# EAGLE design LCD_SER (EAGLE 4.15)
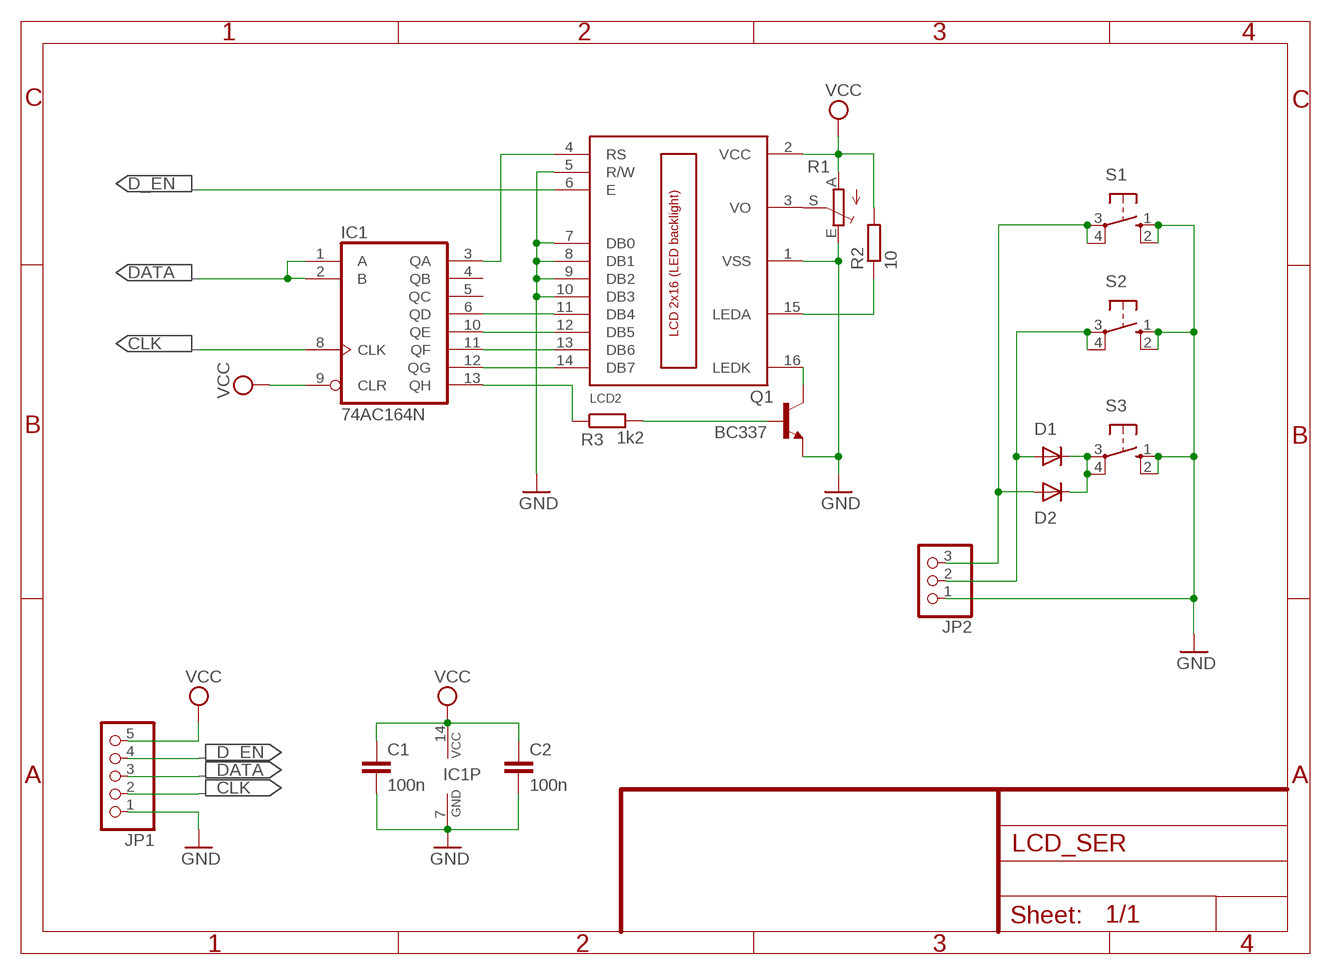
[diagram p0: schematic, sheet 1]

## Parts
C1  100n  C-EU025-025X050  [C025-025X050]
C2  100n  C-EU025-025X050  [C025-025X050]
D1  1N4148  [DO35-10]
D2  1N4148  [DO35-10]
IC1  74AC164N  [DIL14]
JP1  PINHD-1X5  [1X05]
JP2  PINHD-1X3  [1X03]
LCD2  LCD_2X16  [HY-1602F]
Q1  BC337  BC337-16  [TO92]
R1  TRIM_EU-PT10  [PT-10]
R2  10  R-EU_0207/10  [0207/10]
R3  1k2  R-EU_0207/10  [0207/10]
S1  10-XX  [B3F-10XX]
S2  10-XX  [B3F-10XX]
S3  10-XX  [B3F-10XX]

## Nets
CLK: IC1.8(CLK) JP1.2
D_EN: JP1.4 LCD2.6(E)
DATA: IC1.1(A) IC1.2(B) JP1.3
GND: C1.2 C2.2 IC1.7(GND) JP1.1 JP2.1 LCD2.1(VSS) LCD2.5(R/W) LCD2.7(DB0) LCD2.8(DB1) LCD2.9(DB2) LCD2.10(DB3) Q1.1(E) R1.E S1.1(S) S1.2(S1) S2.1(S) S2.2(S1) S3.1(S) S3.2(S1)
N$1: IC1.6(QD) LCD2.11(DB4)
N$2: IC1.10(QE) LCD2.12(DB5)
N$3: IC1.11(QF) LCD2.13(DB6)
N$4: IC1.12(QG) LCD2.14(DB7)
N$5: LCD2.16(LEDK) Q1.3(C)
N$6: IC1.3(QA) LCD2.4(RS)
N$7: LCD2.15(LEDA) R2.1
N$8: IC1.13(QH) R3.1
N$9: LCD2.3(VO) R1.S
N$10: Q1.2(B) R3.2
N$12: D1.C D2.C S3.3(P) S3.4(P1)
N$13: D1.A JP2.2 S2.3(P) S2.4(P1)
N$14: D2.A JP2.3 S1.3(P) S1.4(P1)
VCC: C1.1 C2.1 IC1.9(CLR) IC1.14(VCC) JP1.5 LCD2.2(VCC) R1.A R2.2
Unconnected: IC1.4(QB) IC1.5(QC)

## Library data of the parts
C1 C2 = rcl:C-EU: CAPACITOR, European symbol
D1 D2 = diode:1N4148: DIODE
IC1 = 74xx-eu:74*164: 8-bit parallel out SHIFT REGISTER
JP1 = pinhead:PINHD-1X5: PIN HEADER
JP2 = pinhead:PINHD-1X3: PIN HEADER
LCD2 = lcd_2x16_led_backlight:LCD_2X16
Q1 = transistor-npn:BC337*: NPN Transistor
R1 = pot:TRIM_EU-: POTENTIOMETER
R2 R3 = rcl:R-EU_: RESISTOR, European symbol
S1-S3 = switch-omron:10-XX: OMRON SWITCH

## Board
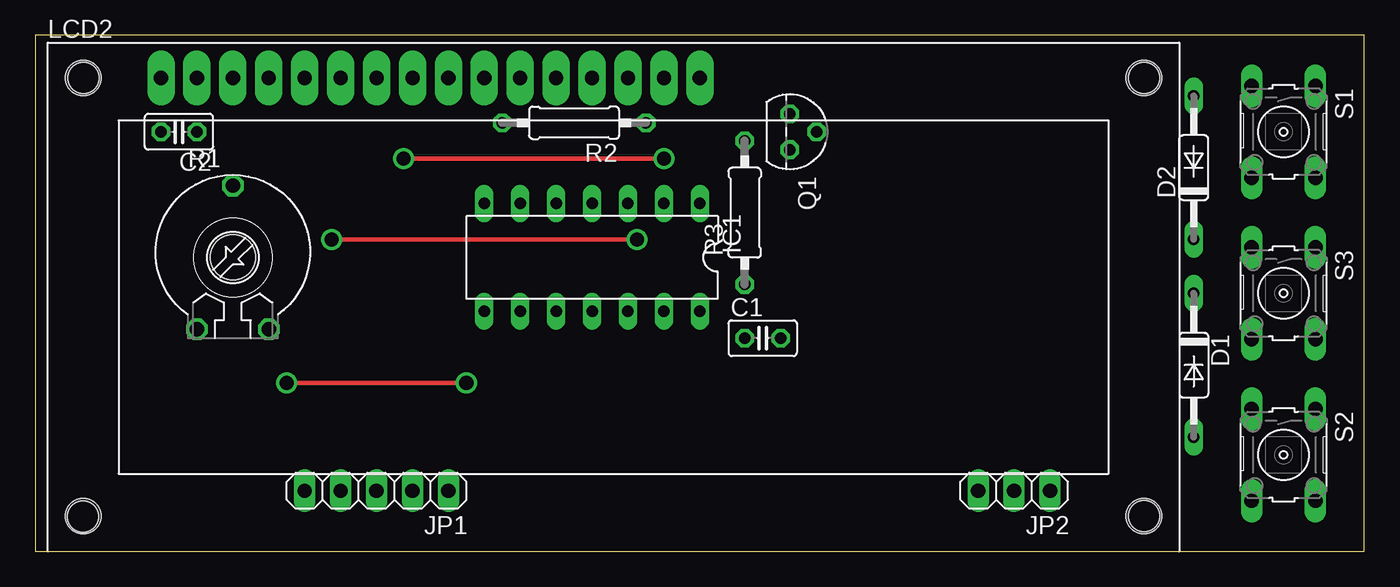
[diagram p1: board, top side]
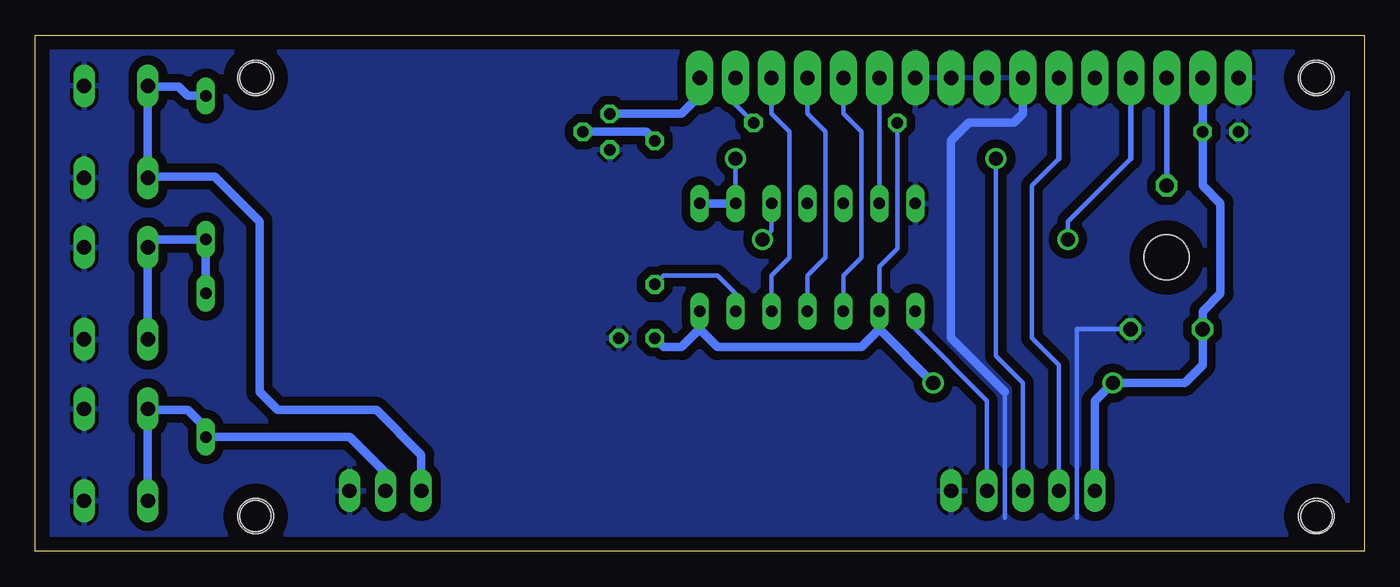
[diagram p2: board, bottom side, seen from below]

Size 93.96 x 36.5 mm. Coordinates in mm from the lower left corner, seen from the top.
Outline: 0,0 93.96,0 93.96,36.5 0,36.5 0,0
Copper layers (1*16): Top 0.035mm / dielectric 1.5mm / Bottom 0.035mm
Design rules "default": minimum track width 10mil, minimum drill 24mil, track to track 8mil, track to pad 8mil, pad to pad 8mil, via to via 8mil, smd to smd 8mil, copper to edge 40mil, drill to drill 8mil, minimum pad ring 10mil, minimum via ring 8mil, stop-mask expansion 4mil, vias tented up to drill 0mil, thermal gap 10mil
Holes 3.2 mm at 13.97,20.79
Holes 2.2 mm at 3.41,33.49 3.38,2.45 78.42,2.48 78.39,33.49

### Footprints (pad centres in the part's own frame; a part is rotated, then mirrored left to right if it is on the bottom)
C025-025X050 = drill 0.813 octagon: 1 -1.27,0; 2 1.27,0
DO35-10 = drill 0.813 long: A 5.08,0; C -5.08,0
DIL14 = drill 0.813 long: 1 -7.62,-3.81; 2 -5.08,-3.81; 3 -2.54,-3.81; 4 0,-3.81; 5 2.54,-3.81; 6 5.08,-3.81; 7 7.62,-3.81; 8 7.62,3.81; 9 5.08,3.81; 10 2.54,3.81; 11 0,3.81; 12 -2.54,3.81; 13 -5.08,3.81; 14 -7.62,3.81
1X05 = drill 1.016 long: 1 -5.08,0; 2 -2.54,0; 3 0,0; 4 2.54,0; 5 5.08,0
1X03 = drill 1.016 long: 1 -2.54,0; 2 0,0; 3 2.54,0
HY-1602F = drill 1 pad 1.93 long: 1 2.54,0; 2 5.08,0; 3 7.62,0; 4 10.16,0; 5 12.7,0; 6 15.24,0; 7 17.78,0; 8 20.32,0; 9 22.86,0; 10 25.4,0; 11 27.94,0; 12 30.48,0; 13 33.02,0; 14 35.56,0; 15 38.1,0; 16 40.64,0 | hole 2.5: -2.96,0; 72.04,0; -2.96,-31; 72.04,-31
TO92 = drill 0.813 octagon: 1 1.27,0; 2 0,1.905; 3 -1.27,0
PT-10 = drill 1.016 octagon: A -2.54,-5.08; E 2.54,-5.08; S 0,5.08
0207/10 = drill 0.813 octagon: 1 -5.08,0; 2 5.08,0
B3F-10XX = drill 1.016 long: 1 -3.251,2.261; 2 3.251,2.261; 3 -3.251,-2.261; 4 3.251,-2.261

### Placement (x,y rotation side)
C1  51.43,15.08 0 top
C2  10.16,29.68 180 top
D1  81.91,13.17 270 top
D2  81.91,27.14 90 top
IC1  39.37,20.79 180 top
JP1  24.12,4.28 180 top
JP2  69.21,4.28 180 top
LCD2  6.34,33.49 0 top
Q1  53.34,29.68 270 top
R1  13.97,20.79 0 top
R2  38.1,30.31 180 top
R3  50.16,23.95 90 top
S1  88.26,29.68 270 top
S2  88.26,6.82 270 top
S3  88.26,18.25 270 top

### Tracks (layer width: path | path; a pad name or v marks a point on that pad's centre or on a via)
CLK
  Bottom 0.305: JP1.2 26.66,10.63 31.74,15.71 IC1.8
D_EN
  Bottom 0.305: 21.58,27.77 23.49,25.87 23.49,15.08 21.58,13.17 JP1.4
  Bottom 0.406: 21.58,27.77 LCD2.6
DATA  (via drill 1)
  Top 0.305: v26.03,27.77 v44.45,27.77
  Bottom 0.305: JP1.3 24.12,11.9 26.03,13.81 v26.03,27.77 | v44.45,27.77 IC1.2
  Bottom 0.61: IC1.2 IC1.1
GND
  Bottom 0.305: R1.E 20.31,15.71 20.31,2.38 | 25.39,2.38 25.39,11.27
  Bottom 0.61: LCD2.7 24.12,30.95 24.76,30.31 27.93,30.31 29.2,29.04 29.2,15.08 25.39,11.27
  pour Bottom (isolate 0.61): 0.63,36.03 93.34,36.03 93.34,0.47 0.63,0.47
N$1
  Bottom 0.305: IC1.6 LCD2.11
N$2
  Bottom 0.305: IC1.10 36.83,19.52 35.55,20.79 35.55,29.68 36.83,30.95 LCD2.12
N$3
  Bottom 0.305: IC1.11 39.37,19.52 38.1,20.79 38.1,29.68 39.37,30.95 LCD2.13
N$4
  Bottom 0.305: IC1.12 41.91,19.52 40.64,20.79 40.64,29.68 41.91,30.95 LCD2.14
N$5
  Bottom 0.61: Q1.3 48.26,30.95 46.98,32.22 LCD2.16
N$6  (via drill 1)
  Top 0.305: v20.95,22.06 v42.54,22.06
  Bottom 0.305: IC1.3 41.91,22.7 v42.54,22.06 | v20.95,22.06 20.95,23.33 16.5,27.77
  Bottom 0.406: 16.5,27.77 LCD2.4
N$7
  Bottom 0.305: R2.1 44.45,31.58 LCD2.15
N$8
  Bottom 0.305: IC1.13 44.45,18.25 45.72,19.52 49.53,19.52 R3.1
N$9
  Bottom 0.406: R1.S LCD2.3
N$10
  Bottom 0.305: R3.2 50.16,29.04
  Bottom 0.61: Q1.2 50.8,29.68 50.16,29.04
N$12
  Bottom 0.305: S3.3 86.28,21.5 86.35,21.42 86,21.07
  Bottom 0.61: D1.C D2.C 85.72,22.06 86.28,21.5 | S3.4 86,21.07
N$13
  Bottom 0.305: 85.8,10.07 85.72,10 86,9.72 | D1.A 81.91,8.73
  Bottom 0.61: 85.8,10.07 S2.3 | 86,9.72 S2.4 | 85.72,10 83.18,10 81.91,8.73 | D1.A 71.75,8.09 69.21,5.55 JP2.2
N$14
  Bottom 0.305: 85.72,32.85 85.8,32.93 S1.3 | S1.4 85.8,26.43 85.72,26.5 86,26.78
  Bottom 0.61: D2.A 83.18,32.22 83.81,32.85 85.72,32.85 | 86,26.78 S1.3 | 85.72,26.5 81.27,26.5 78.1,23.33 78.1,11.27 76.83,10 69.84,10 66.67,6.82 JP2.3
VCC  (via drill 1)
  Top 0.305: v17.77,11.9 v30.47,11.9
  Bottom 0.305: R2.2 33.02,21.42 34.29,20.15 IC1.9
  Bottom 0.61: JP1.5 19.04,10.63 v17.77,11.9 12.7,11.9 11.43,13.17 R1.A 11.43,16.98 10.16,18.25 10.16,24.6 11.43,25.87 C2.1 LCD2.2 | 34.29,15.71 IC1.9 | 34.29,15.71 35.55,14.44 45.72,14.44 46.98,15.71 | 46.98,15.71 IC1.14 | 46.98,15.71 48.26,14.44 49.53,14.44 C1.1 | v30.47,11.9 34.29,15.71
